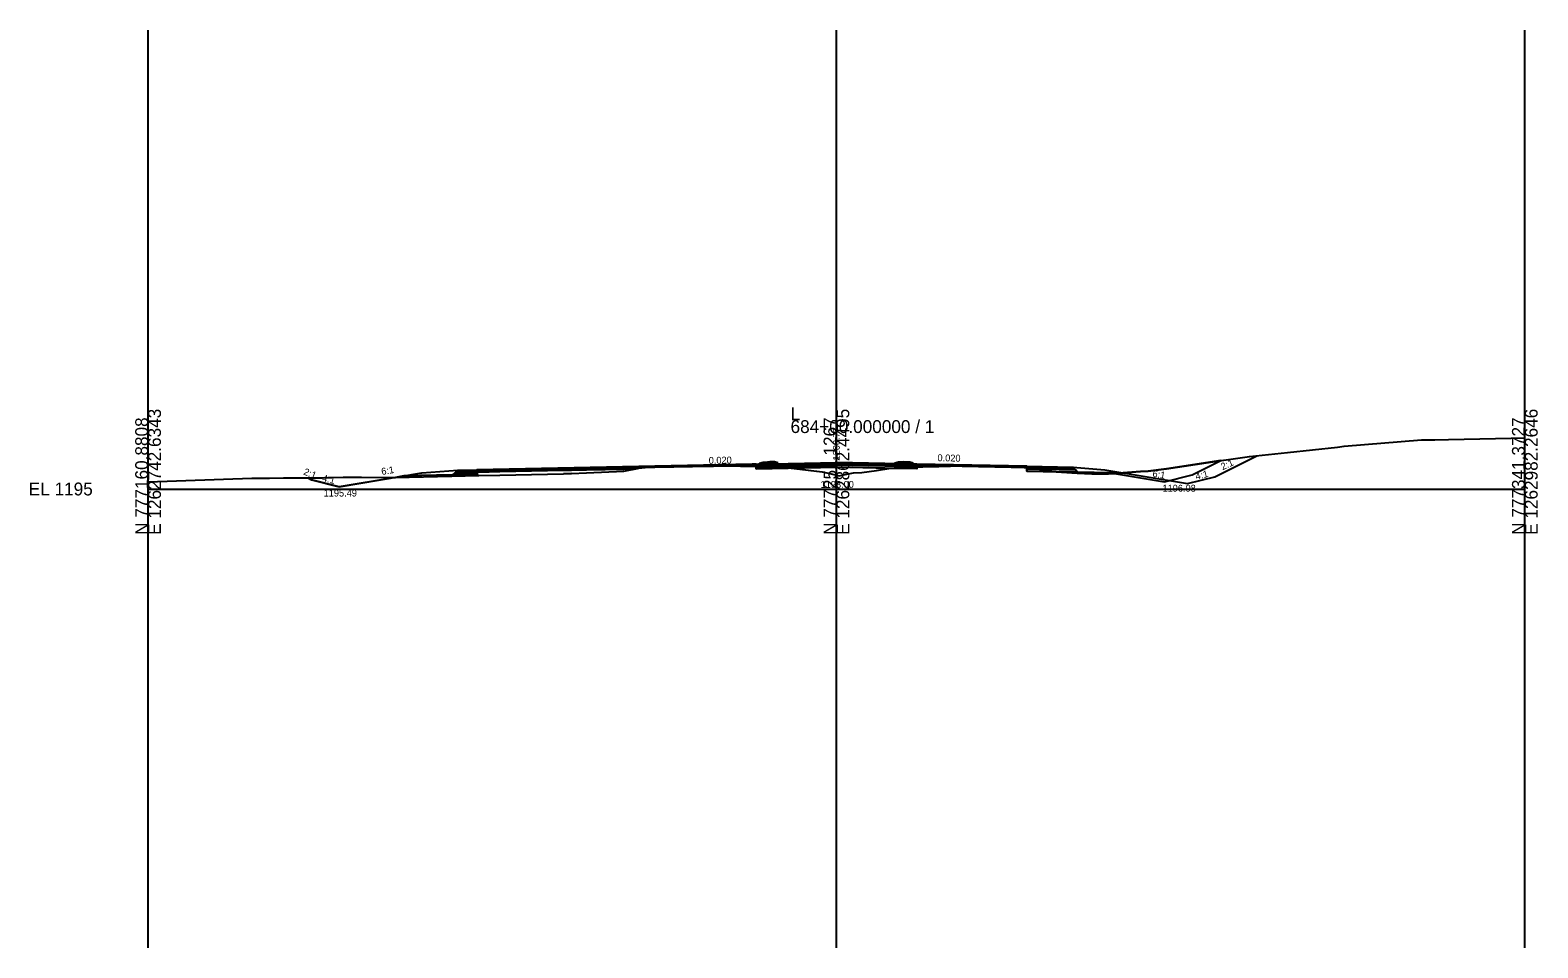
# Model space of a CAD drawing. Extents: x -41 to 1262860, y -100 to 777489.
# Drawn here: x 974.3 to 1302.8, y 545 to 745 of the extents above; entities that cross this region are included whole.
import ezdxf

# ---------------------------------------------------------------- set-up
doc = ezdxf.new("R2010")
doc.units = 0
for name, color, linetype in [('Exist Cross Section Cell', 7, 'Continuous'), ('Exist XS Center Line Elevation Label', 7, 'Continuous'), ('Exist XS Ground Line', 7, 'Continuous'), ('Prop CMT Pvmt Course 1', 7, 'Continuous'), ('Prop CMT Pvmt Surface', 7, 'Continuous'), ('Prop CMT Shld Paved Course 1', 7, 'Continuous'), ('Prop CMT Shld Paved Course 2', 7, 'Continuous'), ('Prop CMT Shld Paved Course 4', 7, 'Continuous'), ('Prop CMT Subgrade Earthwork', 7, 'Continuous'), ('Prop Conc Curb and Gutter', 7, 'Continuous'), ('Prop Conc Island Cover', 7, 'Continuous'), ('Prop XS Ditch Standard Text', 7, 'Continuous'), ('Prop XS Earthwork Shape', 7, 'Continuous'), ('Prop XS Exc Vertical Line 1', 7, 'Continuous'), ('Prop XS Exc Vertical Line 2', 7, 'Continuous'), ('Prop XS Exc Vertical Line 3', 7, 'Continuous'), ('Prop XS Finish Grade', 7, 'Continuous'), ('Prop XS Hydro Elevations', 7, 'Continuous'), ('Prop XS SE Text', 7, 'Continuous'), ('Prop XS Side Slope Text', 7, 'Continuous'), ('Scratch_Level_4', 7, 'Continuous'), ('Scratch_Level_6', 7, 'Continuous')]:
    doc.layers.add(name, color=color, linetype=linetype)

msp = doc.modelspace()

# ---------------------------------------------------------------- linework, layer by layer
at = {"layer": 'Exist Cross Section Cell'}
for p, q in [((1150, 645), (1150, 660)), ((1000, 645), (1150, 645)), ((1150, 645), (1300, 645))]:
    msp.add_line(p, q, dxfattribs=at)
at = {"layer": 'Exist XS Ground Line'}
msp.add_lwpolyline([(1000, 646.58), (1022.63, 647.35), (1026.48, 647.37), (1029.5, 647.41), (1034.99, 647.4), (1037.29, 647.41), (1037.87, 647.42), (1039.16, 647.47), (1040.15, 647.49), (1042.54, 647.56), (1043.72, 647.59), (1044.14, 647.6), (1046.5, 647.59), (1053.47, 647.51), (1054.63, 647.58), (1056.88, 647.6), (1066.17, 647.81), (1072.06, 647.91), (1076.63, 648.01), (1087.03, 648.24), (1090.5, 648.32), (1092.26, 648.35), (1095.54, 648.52), (1103.7, 648.88), (1106.62, 649.46), (1106.96, 649.53), (1110.34, 649.87), (1110.44, 649.88), (1122.8, 650.03), (1123.23, 650.04), (1134.92, 649.88), (1135.06, 649.88), (1139.45, 649.64), (1139.5, 649.64), (1139.57, 649.63), (1146.89, 648.73), (1148.54, 648.35), (1150.62, 647.85), (1151.9, 648.13), (1153.71, 648.49), (1155.5, 648.62), (1158.72, 649.01), (1161.44, 649.51), (1163.69, 649.65), (1165.41, 649.74), (1172.28, 649.91), (1177.41, 650.04), (1184.53, 649.87), (1189.57, 649.74), (1190.91, 649.66), (1193.02, 649.52), (1195.82, 649.06), (1197.44, 648.81), (1202.45, 648.43), (1205.68, 648.34), (1209.29, 648.29), (1216.23, 648.84), (1217.95, 648.92), (1221.93, 649.42), (1234.43, 651.32), (1239.98, 652.07), (1248.31, 652.95), (1259.15, 654.09), (1260.64, 654.3), (1277.48, 655.69), (1280.4, 655.7), (1283.4, 655.78), (1297, 656.1), (1300, 656.12)], dxfattribs=at)
at = {"layer": 'Prop CMT Pvmt Course 1'}
for p in [(1132.5, 650.17), (1167.5, 650.17)]:
    msp.add_line(p, (1150, 650.52), dxfattribs=at)
for points in [[(1071.62, 649.21), (1071.62, 648.96), (1131.66, 650.16), (1131.66, 650.16), (1131.66, 650.16), (1132.5, 650.17), (1132.5, 650.42), (1132.5, 650.42), (1131.66, 650.41), (1131.66, 650.41), (1131.66, 650.41), (1071.62, 649.21), (1071.62, 649.21)], [(1191.5, 649.94), (1191.5, 649.94), (1167.5, 650.42), (1167.5, 650.42), (1167.5, 650.42), (1167.5, 650.17), (1167.5, 650.17), (1191.5, 649.69), (1191.5, 649.94)]]:
    msp.add_lwpolyline(points, dxfattribs=at)
at = {"layer": 'Prop CMT Pvmt Surface'}
for p, q in [((1132.5, 650.42), (1150, 650.77)), ((1167.5, 650.42), (1150, 650.77)), ((1067.5, 649.12), (1071.62, 649.21)), ((1071.62, 649.21), (1132.5, 650.42)), ((1167.5, 650.42), (1191.5, 649.94)), ((1191.5, 649.94), (1201.5, 649.74))]:
    msp.add_line(p, q, dxfattribs=at)
at = {"layer": 'Prop CMT Shld Paved Course 1'}
for p, q in [((1191.5, 649.94), (1191.5, 649.94)), ((1191.5, 649.94), (1191.5, 649.94)), ((1191.5, 649.94), (1191.5, 649.69)), ((1191.5, 649.69), (1191.5, 649.69)), ((1191.5, 649.69), (1201.76, 649.49)), ((1195.5, 649.86), (1195.5, 649.86)), ((1201.76, 649.49), (1201.5, 649.74))]:
    msp.add_line(p, q, dxfattribs=at)
msp.add_lwpolyline([(1067.5, 649.12), (1071.62, 649.21), (1071.62, 649.21), (1071.62, 648.96), (1067.24, 648.87), (1067.24, 648.87), (1067.24, 648.87), (1067.5, 649.12), (1067.5, 649.12)], dxfattribs=at)
at = {"layer": 'Prop CMT Shld Paved Course 2'}
for p, q in [((1071.62, 648.62), (1071.62, 648.96)), ((1071.62, 648.96), (1071.62, 648.96)), ((1071.62, 648.96), (1072.06, 648.96)), ((1072.06, 648.63), (1071.62, 648.62)), ((1072.06, 648.96), (1076.63, 649.06)), ((1072.06, 648.96), (1072.06, 648.96)), ((1076.63, 648.72), (1072.06, 648.63)), ((1072.06, 648.63), (1072.06, 648.63)), ((1076.63, 649.06), (1087.03, 649.26)), ((1076.63, 649.06), (1076.63, 649.06)), ((1076.63, 649.06), (1076.63, 649.06)), ((1087.03, 648.93), (1076.63, 648.72)), ((1076.63, 648.72), (1076.63, 648.72)), ((1076.63, 648.72), (1076.63, 648.72)), ((1087.03, 649.26), (1090.5, 649.33)), ((1087.03, 649.26), (1087.03, 649.26)), ((1090.5, 649), (1087.03, 648.93)), ((1087.03, 648.93), (1087.03, 648.93)), ((1090.5, 649.33), (1092.26, 649.37)), ((1092.26, 649.03), (1090.5, 649)), ((1092.26, 649.37), (1095.54, 649.43)), ((1092.26, 649.37), (1092.26, 649.37)), ((1095.54, 649.1), (1092.26, 649.03)), ((1092.26, 649.03), (1092.26, 649.03)), ((1095.54, 649.43), (1103.7, 649.6)), ((1095.54, 649.43), (1095.54, 649.43)), ((1103.7, 649.26), (1095.54, 649.1)), ((1095.54, 649.1), (1095.54, 649.1)), ((1103.7, 649.6), (1106.62, 649.66)), ((1103.7, 649.6), (1103.7, 649.6)), ((1103.7, 649.6), (1103.7, 649.6)), ((1105.84, 649.31), (1103.7, 649.26)), ((1103.7, 649.26), (1103.7, 649.26)), ((1103.7, 649.26), (1103.7, 649.26)), ((1106.62, 649.46), (1105.84, 649.31)), ((1105.84, 649.31), (1105.84, 649.31)), ((1106.62, 649.66), (1106.62, 649.66)), ((1106.62, 649.66), (1106.96, 649.66)), ((1106.96, 649.53), (1106.62, 649.46)), ((1106.62, 649.46), (1106.62, 649.46)), ((1106.96, 649.66), (1110.34, 649.73)), ((1108.65, 649.7), (1106.96, 649.53)), ((1106.96, 649.66), (1106.96, 649.66)), ((1110.34, 649.73), (1108.65, 649.7)), ((1108.65, 649.7), (1108.65, 649.7)), ((1108.65, 649.7), (1108.65, 649.7)), ((1110.44, 649.73), (1110.34, 649.73)), ((1110.34, 649.73), (1110.34, 649.73)), ((1110.34, 649.73), (1110.34, 649.73)), ((1110.34, 649.73), (1110.44, 649.73)), ((1122.8, 649.98), (1110.44, 649.73)), ((1110.44, 649.73), (1122.8, 649.98)), ((1110.44, 649.73), (1110.44, 649.73)), ((1110.44, 649.73), (1110.44, 649.73)), ((1123.23, 649.99), (1122.8, 649.98)), ((1122.8, 649.98), (1123.23, 649.99)), ((1122.8, 649.98), (1122.8, 649.98)), ((1122.8, 649.98), (1122.8, 649.98)), ((1123.23, 649.99), (1131.66, 650.16)), ((1124.69, 650.02), (1123.23, 649.99)), ((1123.23, 649.99), (1123.23, 649.99)), ((1131.66, 649.93), (1124.69, 650.02)), ((1124.69, 650.02), (1124.69, 650.02)), ((1131.66, 650.16), (1132.5, 650.17)), ((1131.66, 650.16), (1131.66, 650.16)), ((1132.5, 649.91), (1131.66, 649.93)), ((1131.66, 649.93), (1131.66, 649.93)), ((1132.5, 649.84), (1150, 650.19)), ((1132.5, 650.17), (1132.5, 650.17)), ((1132.5, 650.17), (1132.5, 650.17)), ((1132.5, 650.17), (1132.5, 649.91)), ((1132.5, 649.91), (1132.5, 649.84)), ((1167.5, 649.84), (1150, 650.19)), ((1167.5, 649.84), (1167.5, 650.17)), ((1167.5, 650.17), (1167.5, 650.17)), ((1167.5, 650.17), (1167.5, 650.17)), ((1167.5, 650.17), (1172.28, 650.08)), ((1168.54, 649.82), (1167.5, 649.84)), ((1172.28, 649.91), (1168.54, 649.82)), ((1168.54, 649.82), (1168.54, 649.82)), ((1168.54, 649.82), (1168.54, 649.82)), ((1172.28, 650.08), (1172.28, 650.08)), ((1172.28, 650.08), (1177.41, 649.97)), ((1175.99, 650), (1172.28, 649.91)), ((1172.28, 649.91), (1172.28, 649.91)), ((1177.41, 649.97), (1175.99, 650)), ((1175.99, 650), (1175.99, 650)), ((1184.53, 649.83), (1177.41, 649.97)), ((1177.41, 649.97), (1177.41, 649.97)), ((1177.41, 649.97), (1177.41, 649.97)), ((1177.41, 649.97), (1184.53, 649.83)), ((1189.57, 649.73), (1184.53, 649.83)), ((1184.53, 649.83), (1184.53, 649.83)), ((1184.53, 649.83), (1184.53, 649.83)), ((1184.53, 649.83), (1189.57, 649.73)), ((1189.83, 649.73), (1189.57, 649.73)), ((1189.57, 649.73), (1189.57, 649.73)), ((1189.57, 649.73), (1190.91, 649.7)), ((1190.91, 649.66), (1189.83, 649.73)), ((1190.91, 649.7), (1190.91, 649.7)), ((1190.91, 649.7), (1191.5, 649.69)), ((1191.5, 649.62), (1190.91, 649.66)), ((1190.91, 649.66), (1190.91, 649.66)), ((1191.5, 649.69), (1191.5, 649.69)), ((1191.5, 649.69), (1191.5, 649.69)), ((1191.5, 649.69), (1191.5, 649.36)), ((1191.5, 649.69), (1191.5, 649.69)), ((1191.5, 649.69), (1191.5, 649.69)), ((1191.5, 649.69), (1191.5, 649.62)), ((1191.5, 649.62), (1191.5, 649.62)), ((1191.5, 649.36), (1191.5, 649.36)), ((1191.5, 649.36), (1202.1, 649.15)), ((1202.1, 649.15), (1201.76, 649.49))]:
    msp.add_line(p, q, dxfattribs=at)
msp.add_lwpolyline([(1067.24, 648.87), (1071.62, 648.96), (1071.62, 648.96), (1071.62, 648.62), (1066.9, 648.53), (1066.9, 648.53), (1066.9, 648.53), (1067.24, 648.87), (1067.24, 648.87)], dxfattribs=at)
at = {"layer": 'Prop CMT Shld Paved Course 4'}
for p, q in [((1072.06, 647.91), (1071.62, 647.91)), ((1072.06, 647.91), (1076.63, 648.01)), ((1076.63, 648.01), (1087.03, 648.24)), ((1087.03, 648.24), (1090.5, 648.32)), ((1092.26, 648.35), (1090.5, 648.32)), ((1092.26, 648.35), (1095.54, 648.52)), ((1095.54, 648.52), (1103.7, 648.88)), ((1103.7, 648.88), (1105.84, 649.31)), ((1132.5, 649.84), (1132.5, 649.38)), ((1132.5, 649.38), (1150, 649.73)), ((1167.5, 649.38), (1150, 649.73)), ((1167.5, 649.84), (1167.5, 649.38)), ((1168.54, 649.82), (1167.5, 649.79)), ((1191.5, 649.36), (1191.5, 649.36)), ((1191.5, 649.36), (1191.5, 649.36)), ((1191.5, 649.36), (1191.5, 648.9)), ((1191.5, 648.9), (1209.78, 648.54)), ((1202.56, 648.68), (1202.1, 649.15))]:
    msp.add_line(p, q, dxfattribs=at)
msp.add_lwpolyline([(1066.9, 648.53), (1071.62, 648.62), (1071.62, 648.62), (1071.62, 648.16), (1066.44, 648.06), (1066.44, 648.06), (1066.44, 648.06), (1066.9, 648.53), (1066.9, 648.53), (1066.9, 648.53), (1066.9, 648.53)], dxfattribs=at)
at = {"layer": 'Prop CMT Subgrade Earthwork'}
for p, q in [((1071.62, 648.16), (1055.74, 647.85)), ((1071.62, 648.16), (1071.62, 647.91)), ((1132.5, 649.38), (1132.5, 649.91)), ((1150, 649.73), (1132.5, 649.38)), ((1167.5, 649.38), (1150, 649.73)), ((1167.5, 649.79), (1167.5, 649.38)), ((1191.5, 649.62), (1191.5, 648.9)), ((1191.5, 648.9), (1212.73, 648.48))]:
    msp.add_line(p, q, dxfattribs=at)
at = {"layer": 'Prop Conc Curb and Gutter'}
for p, q in [((1133.25, 650.44), (1133.26, 650.6)), ((1133.26, 650.6), (1134.01, 650.85)), ((1133.26, 650.6), (1133.26, 650.6)), ((1134.01, 650.85), (1135.01, 650.87)), ((1134.01, 650.85), (1134.01, 650.85)), ((1135.01, 650.87), (1135.01, 650.44)), ((1136.49, 650.93), (1135.49, 650.95)), ((1135.49, 650.95), (1135.49, 650.52)), ((1137.25, 650.52), (1135.49, 650.52)), ((1135.49, 650.52), (1135.49, 650.39)), ((1135.49, 650.52), (1135.49, 650.52)), ((1137.24, 650.68), (1136.49, 650.93)), ((1136.49, 650.93), (1136.49, 650.93)), ((1137.25, 650.52), (1137.24, 650.68)), ((1137.24, 650.68), (1137.24, 650.68)), ((1137.25, 650.39), (1137.25, 650.52)), ((1137.25, 650.52), (1137.25, 650.52)), ((1137.25, 650.52), (1137.25, 650.52)), ((1162.75, 650.52), (1162.76, 650.68)), ((1162.75, 650.52), (1162.75, 650.52)), ((1162.75, 650.52), (1162.75, 650.39)), ((1164.51, 650.52), (1162.75, 650.52)), ((1162.75, 650.52), (1162.75, 650.52)), ((1162.76, 650.68), (1163.51, 650.93)), ((1162.76, 650.68), (1162.76, 650.68)), ((1163.51, 650.93), (1164.51, 650.95)), ((1163.51, 650.93), (1163.51, 650.93)), ((1164.51, 650.95), (1164.51, 650.52)), ((1164.51, 650.39), (1164.51, 650.52)), ((1164.51, 650.52), (1164.51, 650.52)), ((1165.99, 650.85), (1164.99, 650.87)), ((1164.99, 650.87), (1164.99, 650.44)), ((1166.74, 650.6), (1165.99, 650.85)), ((1165.99, 650.85), (1165.99, 650.85)), ((1166.75, 650.44), (1166.74, 650.6)), ((1166.74, 650.6), (1166.74, 650.6)), ((1133.25, 650.44), (1133.25, 650.44)), ((1133.25, 650.44), (1133.25, 650.31)), ((1135.01, 650.44), (1133.25, 650.44)), ((1133.25, 650.44), (1133.25, 650.44)), ((1133.25, 650.31), (1133.25, 650.31)), ((1133.25, 650.31), (1135.01, 650.31)), ((1135.01, 650.31), (1135.01, 650.44)), ((1135.01, 650.44), (1135.01, 650.44)), ((1135.01, 650.31), (1135.01, 650.31)), ((1135.01, 650.31), (1135.01, 650.31)), ((1135.49, 650.39), (1135.49, 650.39)), ((1135.49, 650.39), (1137.25, 650.39)), ((1137.25, 650.39), (1137.25, 650.39)), ((1137.25, 650.39), (1137.25, 650.39)), ((1162.75, 650.39), (1162.75, 650.39)), ((1162.75, 650.39), (1164.51, 650.39)), ((1164.51, 650.39), (1164.51, 650.39)), ((1164.51, 650.39), (1164.51, 650.39)), ((1166.75, 650.44), (1164.99, 650.44)), ((1164.99, 650.44), (1164.99, 650.31)), ((1164.99, 650.44), (1164.99, 650.44)), ((1164.99, 650.31), (1164.99, 650.31)), ((1164.99, 650.31), (1166.75, 650.31)), ((1166.75, 650.31), (1166.75, 650.44)), ((1166.75, 650.44), (1166.75, 650.44)), ((1166.75, 650.44), (1166.75, 650.44)), ((1166.75, 650.31), (1166.75, 650.31)), ((1166.75, 650.31), (1166.75, 650.31))]:
    msp.add_line(p, q, dxfattribs=at)
at = {"layer": 'Prop Conc Island Cover'}
for p, q in [((1135.49, 650.95), (1135.01, 650.87)), ((1135.01, 650.87), (1135.01, 650.62)), ((1135.49, 650.7), (1135.01, 650.62)), ((1135.49, 650.7), (1135.49, 650.95)), ((1135.49, 650.95), (1135.49, 650.95)), ((1135.49, 650.7), (1135.49, 650.7)), ((1164.51, 650.95), (1164.51, 650.7)), ((1164.99, 650.87), (1164.51, 650.95)), ((1164.99, 650.62), (1164.51, 650.7)), ((1164.99, 650.62), (1164.99, 650.87)), ((1164.99, 650.87), (1164.99, 650.87)), ((1164.99, 650.62), (1164.99, 650.62))]:
    msp.add_line(p, q, dxfattribs=at)
at = {"layer": 'Prop XS Earthwork Shape'}
for points in [[(1210.61, 648.4), (1221.5, 646.58), (1227.5, 648.08), (1233.78, 651.22), (1221.93, 649.42), (1217.95, 648.92), (1216.23, 648.84)], [(1034.99, 647.4), (1037.29, 647.41), (1037.87, 647.42), (1039.16, 647.47), (1040.15, 647.49), (1042.54, 647.56), (1043.72, 647.59), (1044.14, 647.6), (1046.5, 647.59), (1053.47, 647.51), (1053.9, 647.54), (1041.62, 645.49), (1035.62, 646.99), (1034.82, 647.4)], [(1071.62, 648.16), (1066.44, 648.06), (1055.74, 647.85), (1053.9, 647.54), (1054.63, 647.58), (1056.88, 647.6), (1066.17, 647.81), (1071.62, 647.91)], [(1139.45, 649.64), (1139.5, 649.64), (1139.57, 649.63), (1140.33, 649.54), (1132.5, 649.38), (1132.5, 649.91), (1134.92, 649.88), (1135.06, 649.88)], [(1148.54, 648.35), (1150.62, 647.85), (1151.9, 648.13), (1153.71, 648.49), (1155.5, 648.62), (1158.72, 649.01), (1161.4, 649.5), (1150, 649.73), (1140.33, 649.54), (1146.89, 648.73)], [(1161.44, 649.51), (1163.69, 649.65), (1165.41, 649.74), (1167.5, 649.79), (1167.5, 649.38), (1161.4, 649.5)], [(1197.44, 648.81), (1197.87, 648.77), (1191.5, 648.9), (1191.5, 649.62), (1193.02, 649.52), (1195.82, 649.06)], [(1209.29, 648.29), (1210.61, 648.4), (1209.78, 648.54), (1202.56, 648.68), (1197.87, 648.77), (1202.45, 648.43), (1205.68, 648.34)]]:
    msp.add_lwpolyline(points, close=True, dxfattribs=at)
at = {"layer": 'Prop XS Exc Vertical Line 1'}
msp.add_line((1000, 545), (1000, 745), dxfattribs=at)
at = {"layer": 'Prop XS Exc Vertical Line 2'}
msp.add_line((1150, 545), (1150, 745), dxfattribs=at)
at = {"layer": 'Prop XS Exc Vertical Line 3'}
msp.add_line((1300, 545), (1300, 745), dxfattribs=at)
at = {"layer": 'Prop XS Finish Grade'}
for p, q in [((1232.48, 647.68), (1241.6, 652.24)), ((1034.82, 647.4), (1035.62, 646.99)), ((1041.62, 645.49), (1059.62, 648.49)), ((1059.62, 648.49), (1067.5, 649.12)), ((1066.44, 648.06), (1067.5, 649.12)), ((1201.5, 649.74), (1208.48, 649.18)), ((1202.56, 648.68), (1201.5, 649.74)), ((1208.48, 649.18), (1226.48, 646.18)), ((1226.48, 646.18), (1232.48, 647.68)), ((1035.62, 646.99), (1041.62, 645.49))]:
    msp.add_line(p, q, dxfattribs=at)
at = {"layer": 'Scratch_Level_4'}
msp.add_line((1300, 545), (1300, 745), dxfattribs=at)
at = {"layer": 'Scratch_Level_6'}
msp.add_line((1000, 545), (1000, 745), dxfattribs=at)

# ---------------------------------------------------------------- texts
at = {"layer": 'Exist Cross Section Cell'}
for s, p in [('N 777160.8808', (1000, 635)), ('E 1262742.6343', (1002.8, 635)), ('N 777251.1267', (1150, 635)), ('E 1262862.4495', (1152.8, 635)), ('N 777341.3727', (1300, 635)), ('E 1262982.2646', (1302.8, 635))]:
    msp.add_text(s, height=2.8, rotation=90, dxfattribs=at).set_placement(p)
for s, p in [('L', (1140, 660)), ('684+00.000000 / 1', (1140, 657.2)), ('EL 1195', (974, 643.6))]:
    msp.add_text(s, height=2.8, dxfattribs=at).set_placement(p)
at = {"layer": 'Exist XS Center Line Elevation Label'}
msp.add_text('1198.00', height=1.5, dxfattribs=at).set_placement((1146.55, 645.25))
at = {"layer": 'Prop XS Ditch Standard Text'}
for s, p in [('1195.49', (1038.26, 643.36)), ('1196.08', (1221.05, 644.42))]:
    msp.add_text(s, height=1.5, dxfattribs=at).set_placement(p)
at = {"layer": 'Prop XS Hydro Elevations'}
msp.add_text('1200.77', height=1.5, rotation=90, dxfattribs=at).set_placement((1150.73, 651.22))
at = {"layer": 'Prop XS SE Text'}
for rotation, p in [(1.1458, (1122.18, 650.47)), (358.8542, (1172.01, 651.06))]:
    msp.add_text('0.020', height=1.5, rotation=rotation, dxfattribs=at).set_placement(p)
at = {"layer": 'Prop XS Side Slope Text'}
for s, rotation, p in [('2:1', 24.7387, (1234.16, 649.08)), ('2:1', 338.2726, (1033.74, 648.21)), ('4:1', 345.9638, (1037.83, 646.75)), ('6:1', 9.4623, (1050.95, 648.05)), ('6:1', 350.5377, (1218.79, 647.67)), ('4:1', 14.0362, (1228.42, 646.98))]:
    msp.add_text(s, height=1.5, rotation=rotation, dxfattribs=at).set_placement(p)

doc.saveas('drawing.dxf')
